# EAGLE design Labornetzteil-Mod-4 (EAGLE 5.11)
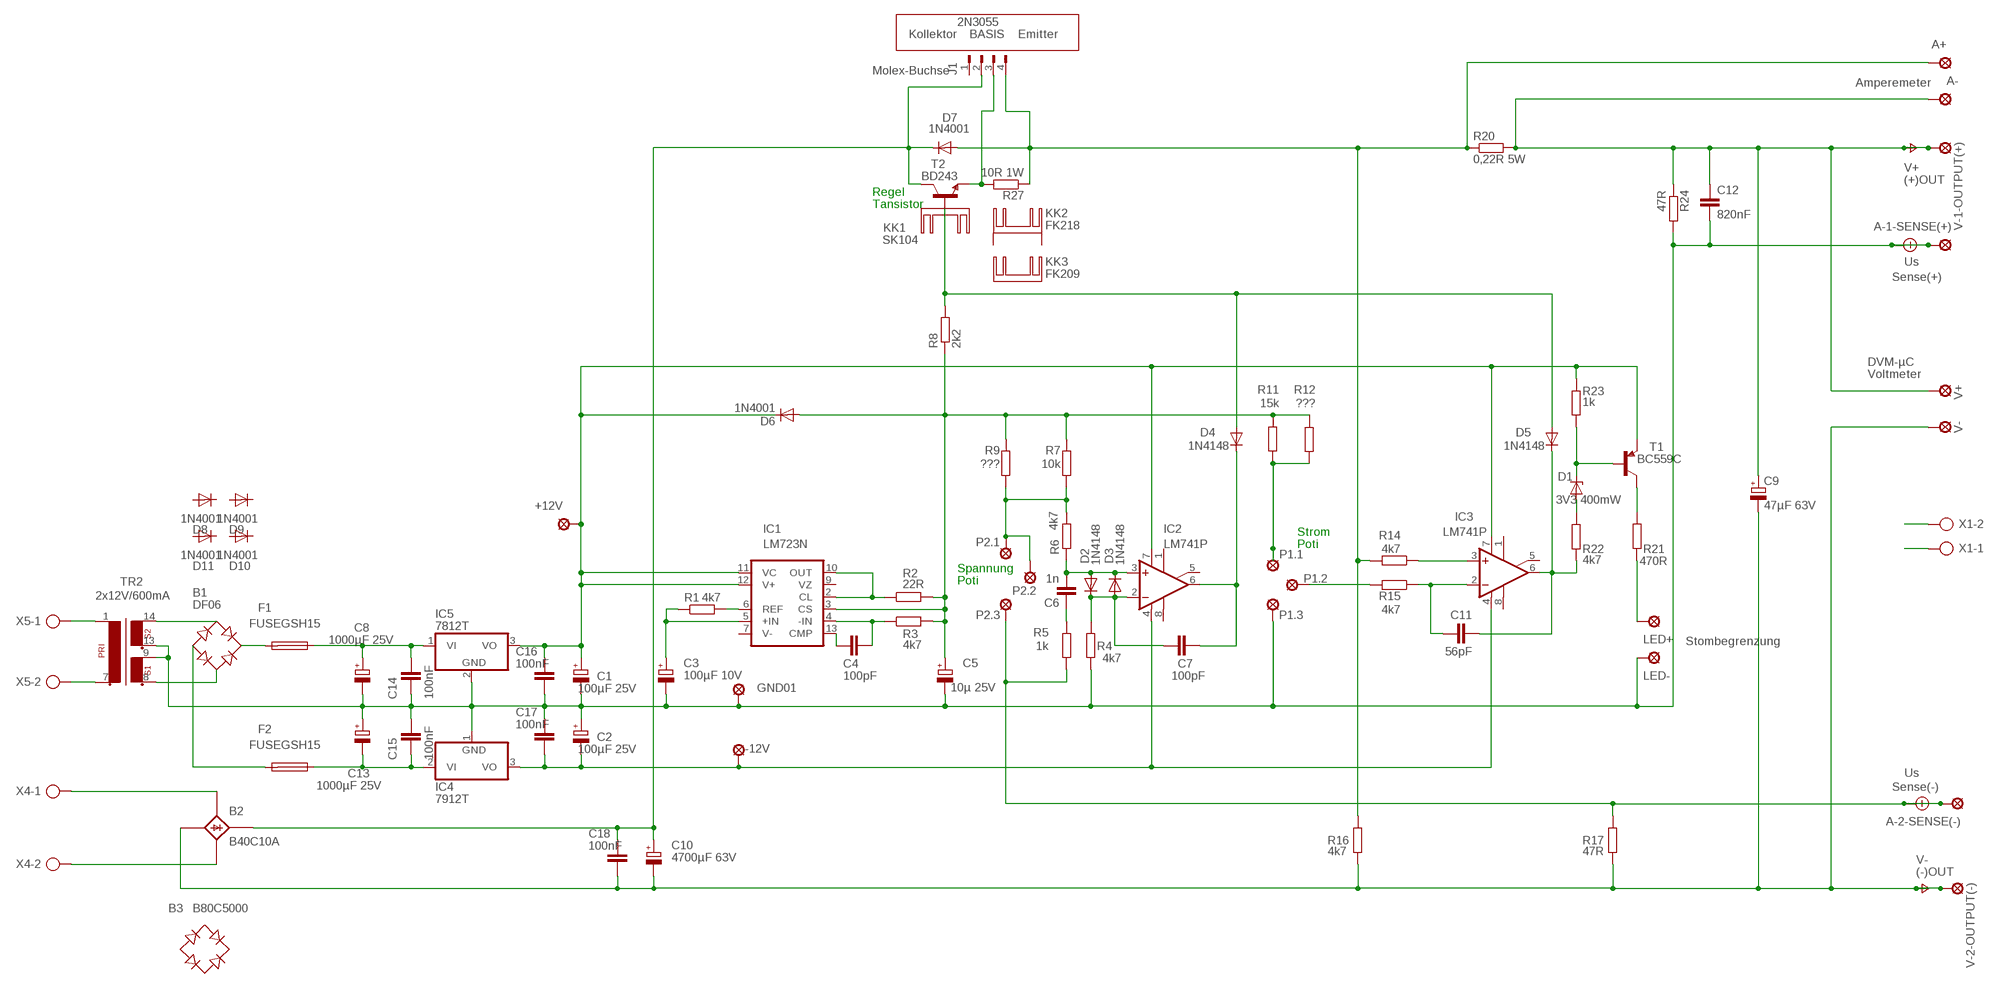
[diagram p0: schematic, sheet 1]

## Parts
+12V  SE14  [SE14]
-12V  SE14  [SE14]
A+  SE14  [SE14]
A-  SE14  [SE14]
A-1-SENSE(+)  SE14  [SE14]
A-2-SENSE(-)  SE14  [SE14]
B1  DF06  B-DIL  [B-DIL]
B2  B40C10A  B25A-  [B25A-]
B3  B80C5000  RECTIFIER-SKB32  [SKB32]
C1  100µF 25V  CPOL-EUE5-8.5  [E5-8,5]
C2  100µF 25V  CPOL-EUE5-8.5  [E5-8,5]
C3  100µF 10V  CPOL-EUE5-8.5  [E5-8,5]
C4  100pF  C-EU025-024X044  [C025-024X044]
C5  10µ 25V  CPOL-EUE5-8.5  [E5-8,5]
C6  1n  C-EU025-024X044  [C025-024X044]
C7  100pF  C-EU025-024X044  [C025-024X044]
C8  1000µF 25V  CPOL-EUE5-8.5  [E5-8,5]
C9  47µF 63V  CPOL-EUE3.5-8  [E3,5-8]
C10  4700µF 63V  CPOL-EUE10-35  [EB35D]
C11  56pF  C-EU025-024X044  [C025-024X044]
C12  820nF  C-EU025-024X044  [C025-024X044]
C13  1000µF 25V  CPOL-EUE5-8.5  [E5-8,5]
C14  100nF  C-EU025-030X050  [C025-030X050]
C15  100nF  C-EU025-030X050  [C025-030X050]
C16  100nF  C-EU025-030X050  [C025-030X050]
C17  100nF  C-EU025-030X050  [C025-030X050]
C18  100nF  C-EU025-030X050  [C025-030X050]
D1  3V3 400mW  ZENER-DIODEDO34-7  [DO34Z7]
D2  1N4148  1N4148DO35-10  [DO35-10]
D3  1N4148  1N4148DO35-10  [DO35-10]
D4  1N4148  1N4148DO35-10  [DO35-10]
D5  1N4148  1N4148DO35-10  [DO35-10]
D6  1N4001  1N4004  [DO41-10]
D7  1N4001  1N4004  [DO41-10]
D8  1N4001  1N4004  [DO41-10]
D9  1N4001  1N4004  [DO41-10]
D10  1N4001  1N4004  [DO41-10]
D11  1N4001  1N4004  [DO41-10]
F1  FUSEGSH15  [GSH15]
F2  FUSEGSH15  [GSH15]
GND01  SE14  [SE14]
IC1  LM723N  [DIL14]
IC2  LM741P  [DIL08]
IC3  LM741P  [DIL08]
IC4  7912T  7915T  [TO220H]
IC5  7812T  7815T  [TO220H]
J1  FLOPPY-4  [FLOPPY-4]
KK1  SK104  [SK104]
KK2  FK218  [FK218]
KK3  FK209  [FK209]
LED+  SE14  [SE14]
LED-  SE14  [SE14]
P1.1  SE14  [SE14]
P1.2  SE14  [SE14]
P1.3  SE14  [SE14]
P2.1  SE14  [SE14]
P2.2  SE14  [SE14]
P2.3  SE14  [SE14]
R1  4k7  R-EU_0204/2V  [0204V]
R2  22R  R-EU_0204/2V  [0204V]
R3  4k7  R-EU_0204/2V  [0204V]
R4  4k7  R-EU_0207/10  [0207/10]
R5  1k  R-EU_0207/10  [0207/10]
R6  4k7  R-EU_0207/10  [0207/10]
R7  10k  R-EU_0207/10  [0207/10]
R8  2k2  R-EU_0207/10  [0207/10]
R9  ???  R-EU_0207/10  [0207/10]
R11  15k  R-EU_0207/10  [0207/10]
R12  ???  R-EU_0207/10  [0207/10]
R14  4k7  R-EU_0207/10  [0207/10]
R15  4k7  R-EU_0207/10  [0207/10]
R16  4k7  R-EU_0207/10  [0207/10]
R17  47R  R-EU_0207/10  [0207/10]
R20  0,22R 5W  R-EU_0617/22  [0617/22]
R21  470R  R-EU_0207/10  [0207/10]
R22  4k7  R-EU_0207/10  [0207/10]
R23  1k  R-EU_0207/10  [0207/10]
R24  47R  R-EU_0207/10  [0207/10]
R27  10R 1W  R-EU_0309/12  [0309/12]
T1  BC559C  -PNP-TO92  [TO92]
T2  BD243  [TO220]
TR2  2x12V/600mA  EI54-2  [EI54-2]
V+  SE14  [SE14]
V-  SE14  [SE14]
V-1-OUTPUT(+)  V(+) Output  SE14  [SE14]
V-2-OUTPUT(-)  V(-) Output  SE14  [SE14]
X1  AK300/2  [AK300/2]
X4  AK300/2  [AK300/2]
X5  AK300/2  [AK300/2]

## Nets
+US: A-1-SENSE(+).MP C1.- C2.+ C3.- C5.- C8.- C12.2 C13.+ C14.1 C15.2 C16.1 C17.2 GND01.MP IC4.1(GND) IC5.2(GND) LED-.MP P1.3.MP R4.1 R24.2 TR2.9 TR2.13 ; supply symbol labelled Us
-US: A-2-SENSE(-).MP P2.3.MP R5.1 R17.1 ; supply symbol labelled Us
GND: B2.-1(-) C9.- C10.- C18.1 R16.2 R17.2 V-2-OUTPUT(-).MP V-.MP X1.1 ; supply symbol labelled V-
N$1: C3.+ IC1.5(+IN) R1.1
N$2: B1.AC1 TR2.14
N$3: B1.AC2 TR2.8
N$4: TR2.1 X5.1
N$5: IC1.6(REF) R1.2
N$6: -12V.MP C2.- C17.1 IC2.4(V-) IC3.4(V-) IC4.3(VO)
N$7: C6.1 R5.2
N$8: P2.1.MP P2.2.MP R6.2 R7.1 R9.1
N$9: IC1.2(CL) IC1.10(OUT) R2.1
N$10: C4.2 IC1.4(-IN) R3.1
N$11: TR2.7 X5.2
N$12: C4.1 IC1.13(CMP)
N$13: LED+.MP R21.1
N$14: C5.+ D6.A IC1.3(CS) R2.2 R3.2 R7.2 R8.1 R9.2 R11.2 R12.1
N$15: C6.2 D2.A D3.C IC2.3(+IN) R6.1
N$16: C7.1 D2.C D3.A IC2.2(-IN) R4.2
N$17: D4.A D5.A R8.2 T2.1(B)
N$18: C7.2 D4.C IC2.6(OUT)
N$19: P1.1.MP R11.1 R12.2
N$21: R21.2 T1.3(C)
N$22: IC3.3(+IN) R14.1
N$23: D1.C R23.2 T1.2(B)
N$24: P1.2.MP R15.2
N$25: D1.A R22.1
N$27: A+.MP D7.A J1.4 R14.2 R16.1 R20.1 R27.1
N$31: B2.AC1-(AC1) X4.1
N$32: B2.AC2-(AC2) X4.2
N$33: C11.1 IC3.2(-IN) R15.1
N$34: C11.2 D5.C IC3.6(OUT) R22.2
N$35: +12V.MP C1.+ C16.2 D6.C IC1.11(VC) IC1.12(V+) IC2.7(V+) IC3.7(V+) IC5.3(VO) R23.1 T1.1(E)
N$37: B2.+1(+) C10.+ C18.2 D7.C J1.2 T2.2(C)
N$38: C8.+ C14.2 F1.1 IC5.1(VI)
N$39: B1.- F2.2
N$40: C13.- C15.1 F2.1 IC4.2(VI)
N$41: B1.+ F1.2
N$42: J1.3 R27.2 T2.3(E)
V+: A-.MP C9.+ C12.1 R20.2 R24.1 V+.MP V-1-OUTPUT(+).MP X1.2
Unconnected: B2.+ B2.- B2.AC1 B2.AC2 B3.+ B3.- B3.AC1 B3.AC2 D8.A D8.C D9.A D9.C D10.A D10.C D11.A D11.C IC1.7(V-) IC1.9(VZ) IC2.1(ON1) IC2.5(ON2) IC2.8(OPT) IC3.1(ON1) IC3.5(ON2) IC3.8(OPT) J1.1 KK2.A2,2(K) KK2.B2,2(K)

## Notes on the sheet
- 2N3055
- Kollektor | BASIS | Emitter
- Molex-Buchse
- Amperemeter
- (+)OUT
- Regel
- Tansistor
- Sense(+)
- DVM-µC
- Voltmeter
- Strom
- Poti
- Spannung
- Poti
- Stombegrenzung
- Sense(-)
- (-)OUT

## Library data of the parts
+12V -12V A+ A- A-1-SENSE(+) A-2-SENSE(-) GND01 LED+ LED- P1.1-P1.3 P2.1-P2.3 V+ V- V-1-OUTPUT(+) V-2-OUTPUT(-) = solpad:SE14: SOLDER PAD
B1 = rectifier:B-DIL: RECTIFIER
B2 = rectifier:B25A-: RECTIFIER 25-A bridge
B3 = rectifier:RECTIFIER-: Rectifier
C1-C3 C5 C8-C10 C13 = rcl:CPOL-EU: POLARIZED CAPACITOR, European symbol
C4 C6 C7 C11 C12 C14-C18 = rcl:C-EU: CAPACITOR, European symbol
D1 = diode:ZENER-DIODE: Z-Diode
D2-D5 = diode:1N4148: DIODE
D6-D11 = diode:1N4004: DIODE
F1 F2 = fuse:FUSE: Fuse; OC_FARNELL: unknown; OC_NEWARK: unknown
IC1 = linear:*723: Positive VOLTAGE REGULATOR
IC2 IC3 = linear:*741: OP AMP
IC4 = linear:79*: Negative VOLTAGE REGULATOR
IC5 = linear:78*: Positive VOLTAGE REGULATOR Source: http://cache.national.com/ds/LM/LM78L05.pdf http://www.fairchildsemi.com/ds/LM/LM7805.pdf
J1 = con-amp:FLOPPY-4: MATE N-LOCK Floppy / HDD conector Distributor: Bürklin 71F970; OC_FARNELL: unknown; OC_NEWARK: unknown
KK1 = heatsink:SK104: HEATSINK
KK2 = heatsink:FK218: HEATSINK
KK3 = heatsink:FK209: HEATSINK
R1-R9 R11 R12 R14-R17 R20-R24 R27 = rcl:R-EU_: RESISTOR, European symbol
T1 = transistor:*-PNP-: PNP Transistror
T2 = transistor:BD243: NPN TRANSISTOR Source: Motorola Semiconductor, Master Selection Guide Q3/95 SG73 REV 8 page 5.5-4
TR2 = trafo:EI54-2: TRANSFORMER 1 primary winding, 2 secondary windings ERA
X1 X4 X5 = con-ptr500:AK300/2: CONNECTOR; OC_FARNELL: unknown; OC_NEWARK: unknown

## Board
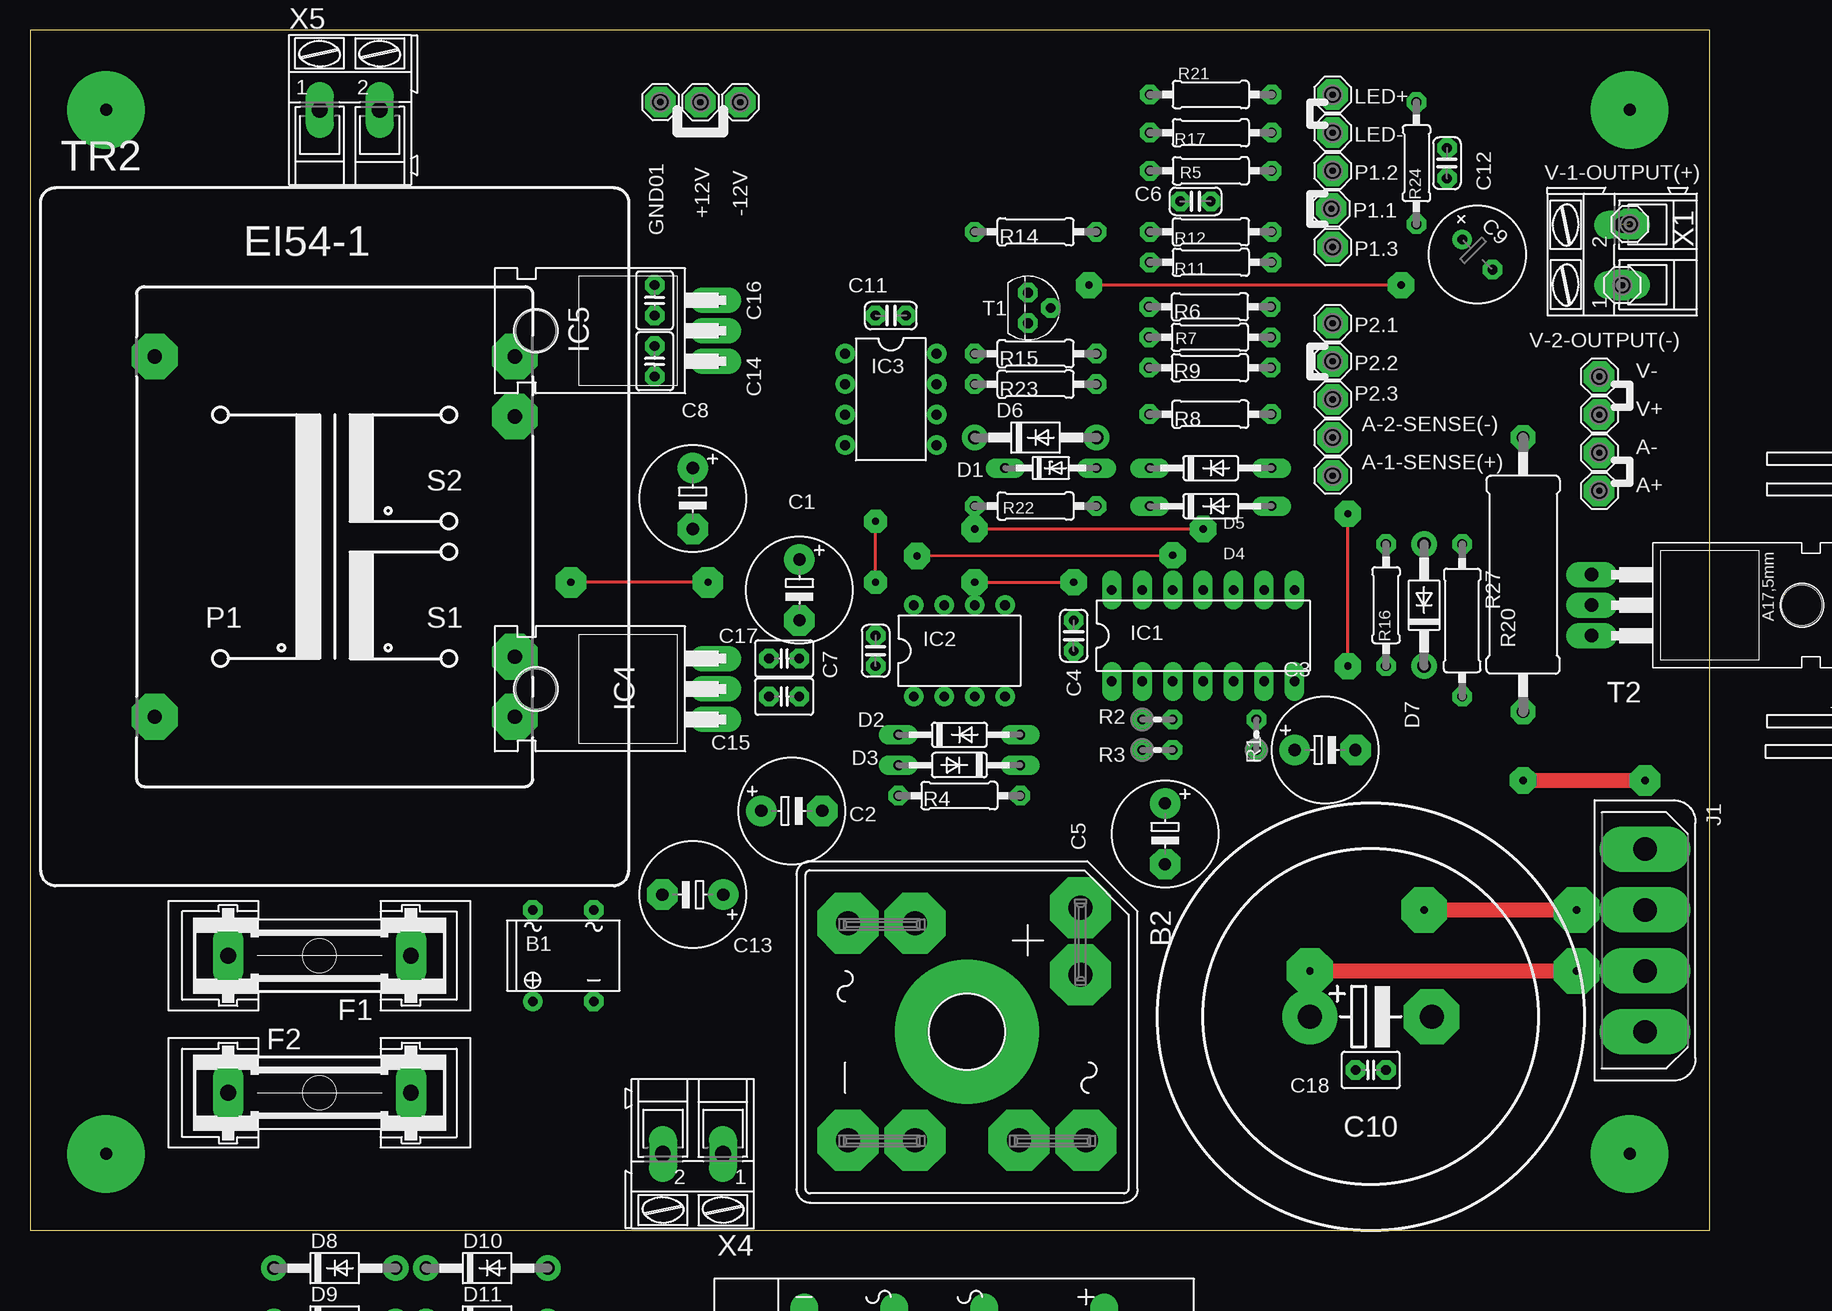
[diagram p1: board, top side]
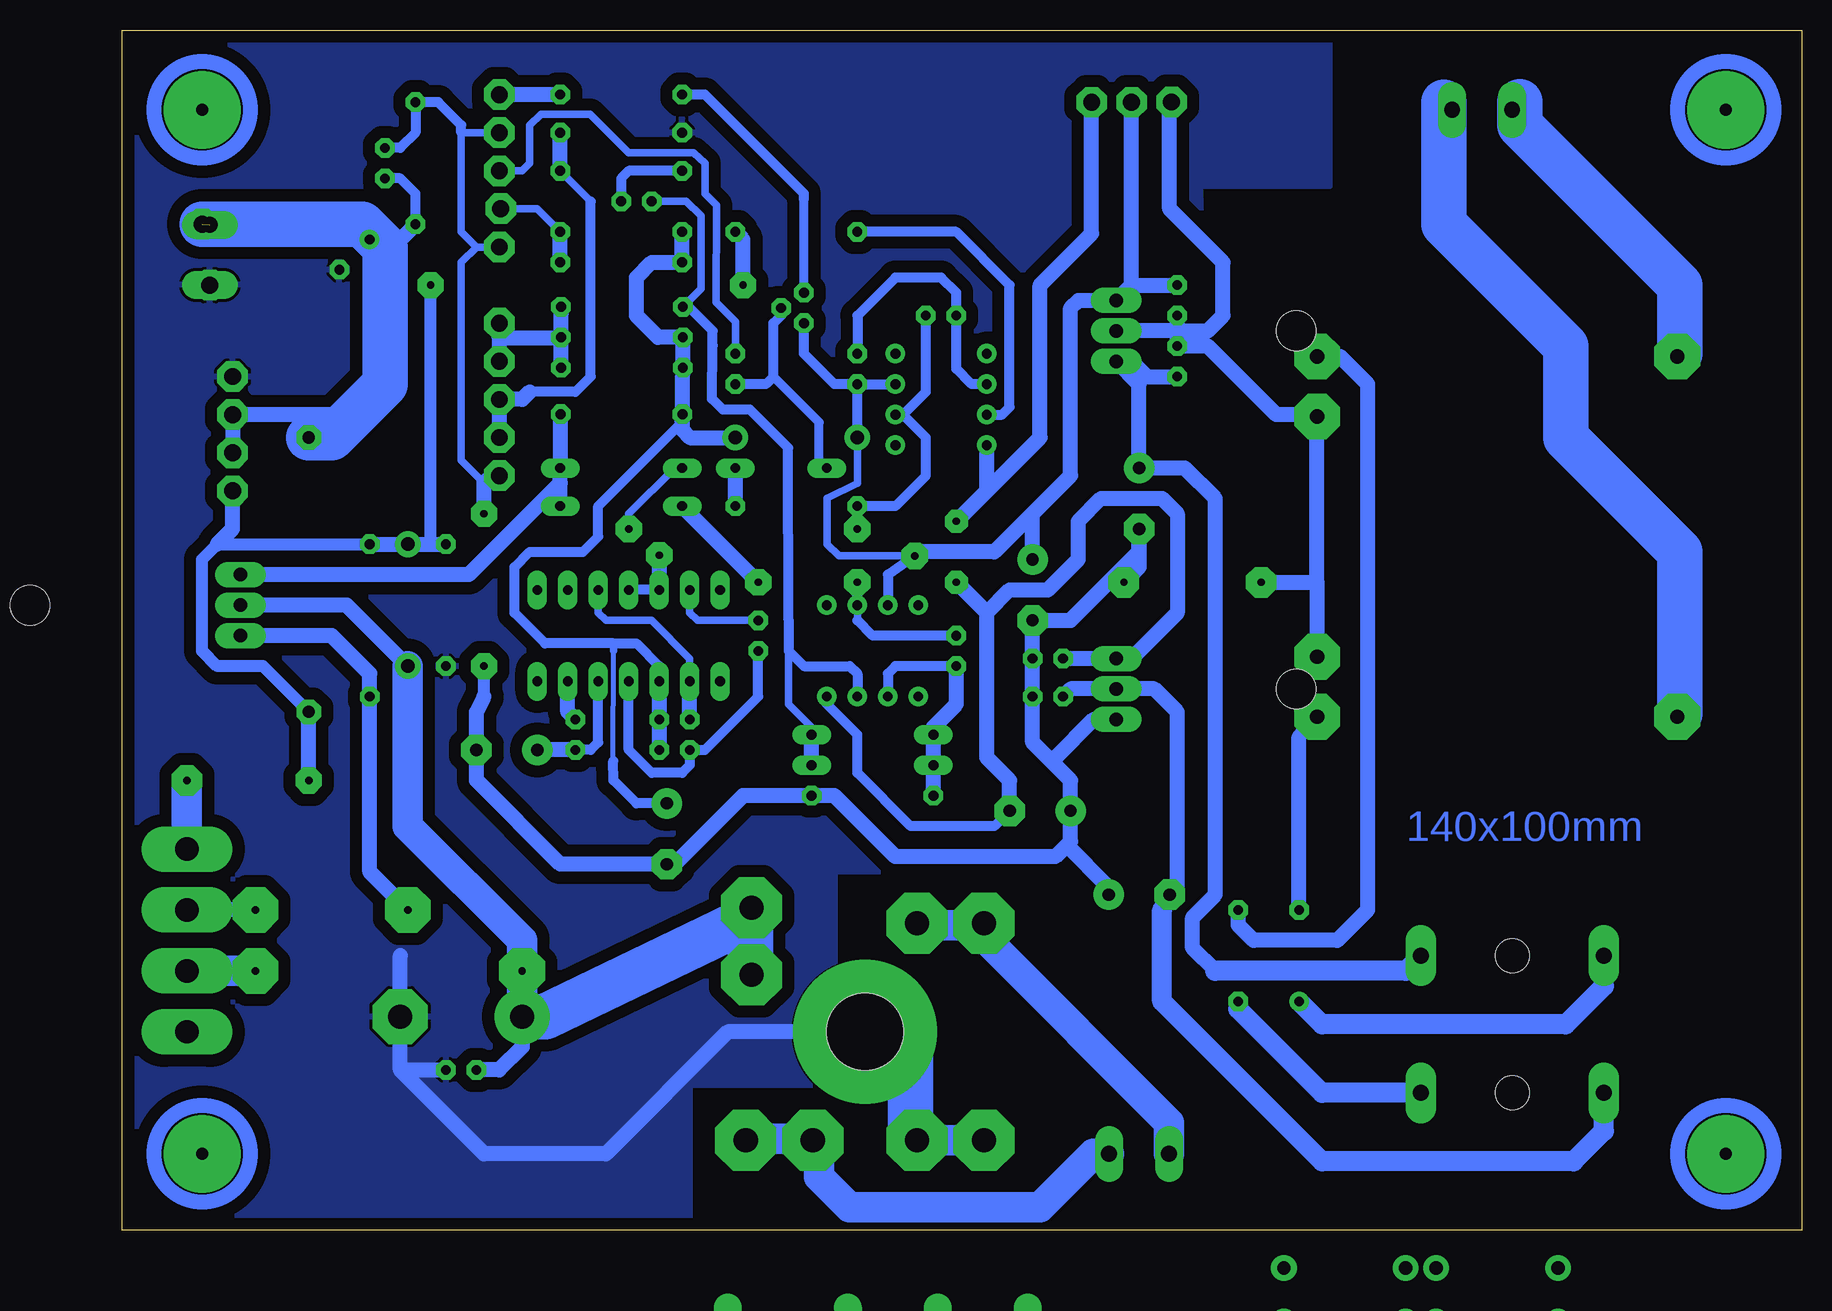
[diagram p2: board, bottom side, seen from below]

Size 140 x 100 mm. Coordinates in mm from the lower left corner, seen from the top.
Outline: 0,0 140,0 140,100 0,100 0,0
Copper layers (1*16): Top 0.035mm / dielectric 1.5mm / Bottom 0.035mm
Design rules "default *": minimum track width 30mil, minimum drill 24mil, track to track 8mil, track to pad 8mil, pad to pad 8mil, via to via 8mil, smd to smd 8mil, copper to edge 0.5mm, drill to drill 8mil, minimum pad ring 10mil, minimum via ring 8mil, stop-mask expansion 4mil, vias tented up to drill 0mil, thermal gap 10mil

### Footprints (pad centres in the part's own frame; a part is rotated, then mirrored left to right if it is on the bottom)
SE14 = drill 1.397 pad 2.54 octagon: MP 0,0
B-DIL = drill 0.813 round: + -2.54,-3.81 | drill 0.813 octagon: - 2.54,-3.81; AC1 2.54,3.81; AC2 -2.54,3.81
B25A- = drill 2.007 pad 5.08 octagon: + -10.338,9.449; +1 -4.75,9.449; - 9.042,-4.343; -1 9.042,-9.931; AC1 9.042,4.343; AC1- 9.042,9.931; AC2 -9.042,-4.343; AC2- -9.042,-9.931 | hole 6.401: 0,0
SKB32 = drill 1.321 long: + -13.97,0; - 11.024,0; AC1 -3.962,0; AC2 3.531,0
E5-8,5 = drill 1.016 pad 2.54 round: + -2.54,0 | drill 1.016 pad 2.54 octagon: - 2.54,0
C025-024X044 = drill 0.813 octagon: 1 -1.27,0; 2 1.27,0
E3,5-8 = drill 0.813 pad 1.6 round: + -1.778,0 | drill 0.813 pad 1.6 octagon: - 1.778,0
EB35D = drill 2.007 pad 4.597 round: + -5.08,0 | drill 2.007 pad 4.597 octagon: - 5.08,0
C025-030X050 = drill 0.813 octagon: 1 -1.27,0; 2 1.27,0
DO34Z7 = drill 0.813 long: A 3.81,0; C -3.81,0
DO35-10 = drill 0.813 long: A 5.08,0; C -5.08,0
DO41-10 = drill 1.118 round: A 5.08,0; C -5.08,0
GSH15 = drill 1.321 pad 2.54 long: 1 -7.62,0; 2 7.62,0 | hole 2.794: 0,0
DIL14 = drill 0.813 long: 1 -7.62,-3.81; 2 -5.08,-3.81; 3 -2.54,-3.81; 4 0,-3.81; 5 2.54,-3.81; 6 5.08,-3.81; 7 7.62,-3.81; 8 7.62,3.81; 9 5.08,3.81; 10 2.54,3.81; 11 0,3.81; 12 -2.54,3.81; 13 -5.08,3.81; 14 -7.62,3.81
DIL08 = drill 0.813 pad 1.27 round: 1 -3.81,-3.81; 2 -1.27,-3.81; 3 1.27,-3.81; 4 3.81,-3.81; 5 3.81,3.81; 6 1.27,3.81; 7 -1.27,3.81; 8 -3.81,3.81
TO220H = drill 1.118 long: 1 -2.54,-10.16; 2 0,-10.16; 3 2.54,-10.16 | hole 3.302: 0,4.826
FLOPPY-4 = drill 1.93 pad 3.81 long: 1 7.62,0; 2 2.54,0; 3 -2.54,0; 4 -7.62,0
SK104 = hole 2.54: -12.7,-0.762; 12.7,-0.762
FK218 = drill 2.21 pad 3.81 round: A2,2 -8.89,-0.508; B2,2 8.89,-0.508
0204V = drill 0.813 octagon: 1 -1.27,0; 2 1.27,0
0207/10 = drill 0.813 octagon: 1 -5.08,0; 2 5.08,0
0617/22 = drill 1.016 octagon: 1 -11.43,0; 2 11.43,0
0309/12 = drill 0.813 octagon: 1 -6.35,0; 2 6.35,0
TO92 = drill 0.813 octagon: 1 1.27,0; 2 0,1.905; 3 -1.27,0
TO220 = drill 1.118 long: 1 -2.54,-6.35; 2 0,-6.35; 3 2.54,-6.35 | hole 3.302: 0,11.176
EI54-2 = drill 1.194 pad 3.81 octagon: 1 -15.011,15.011; 7 -15.011,-15.011; 8 15.011,-15.011; 9 15.011,-10.008; 13 15.011,10.008; 14 15.011,15.011
AK300/2 = drill 1.321 long: 1 -2.515,0; 2 2.489,0

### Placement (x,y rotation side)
+12V  55.88,93.98 0 top
-12V  59.2,93.98 0 top
A+  130.81,61.59 0 top
A-  130.81,64.77 0 top
A-1-SENSE(+)  108.58,62.87 0 top
A-2-SENSE(-)  108.58,66.04 0 top
B1  44.45,22.86 0 top
B2  78.11,16.51 270 top
B3  not placed on the board
C1  64.14,53.34 270 top
C2  63.5,34.92 0 top
C3  107.95,40.01 0 top
C4  87,49.53 270 top
C5  94.61,33.02 270 top
C6  97.16,85.72 180 top
C7  70.48,48.26 90 top
C8  55.24,60.96 270 top
C9  120.65,81.28 315.1 top
C10  111.76,17.78 0 top
C11  71.75,76.2 0 top
C12  118.11,88.9 90 top
C13  55.24,27.94 180 top
C14  52.07,72.39 270 top
C15  62.87,44.45 0 top
C16  52.07,77.47 90 top
C17  62.87,47.62 0 top
C18  111.76,13.34 180 top
D1  85.09,63.5 0 top
D2  77.47,41.27 0 top
D3  77.47,38.73 180 top
D4  98.42,60.33 0 top
D5  98.42,63.5 0 top
D6  83.82,66.04 0 top
D7  116.2,52.07 90 top
D8  not placed on the board
D9  not placed on the board
D10  not placed on the board
D11  not placed on the board
F1  24.13,22.86 180 top
F2  24.13,11.43 0 top
GND01  52.55,93.99 0 top
IC1  97.79,49.53 0 top
IC2  77.47,48.26 0 top
IC3  71.75,69.22 270 top
IC4  46.99,45.09 90 top
IC5  46.99,74.93 90 top
J1  134.62,24.13 270 top
KK1  not placed on the board
KK2  not placed on the board
KK3  not placed on the board
LED+  108.58,94.61 0 top
LED-  108.58,91.44 0 top
P1.1  108.47,85.11 0 top
P1.2  108.58,88.27 0 top
P1.3  108.58,81.92 0 top
P2.1  108.58,75.56 0 top
P2.2  108.58,72.39 0 top
P2.3  108.58,69.22 0 top
R1  102.23,41.27 90 top
R2  93.98,42.55 0 top
R3  93.98,40.01 0 top
R4  77.47,36.2 180 top
R5  98.42,88.27 180 top
R6  98.36,76.94 0 top
R7  98.36,74.39 180 top
R8  98.39,67.99 0 top
R9  98.36,71.86 180 top
R11  98.42,80.64 180 top
R12  98.42,83.19 0 top
R14  83.82,83.19 0 top
R15  83.82,73.03 0 top
R16  113.03,52.07 270 top
R17  98.42,91.44 180 top
R20  124.46,54.61 90 top
R21  98.42,94.61 180 top
R22  83.82,60.33 180 top
R23  83.82,70.48 0 top
R24  115.57,88.9 90 top
R27  119.38,50.8 270 top
T1  83.19,76.83 270 top
T2  136.53,52.07 270 top
TR2  25.4,57.78 0 top
V+  130.81,67.94 0 top
V-  130.81,71.12 0 top
V-1-OUTPUT(+)  133.35,83.82 0 top
V-2-OUTPUT(-)  132.72,78.74 0 top
X1  132.72,81.28 90 top
X4  55.24,6.35 180 top
X5  26.67,93.34 0 top

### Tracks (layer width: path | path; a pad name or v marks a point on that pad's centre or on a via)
+US  (via drill 0.61 pad 2.18, 0.61 pad 2.54)
  Top 0.254: v109.86,46.99 v109.86,59.69 | v56.52,53.98 v45.09,53.98
  Bottom 0.61: LED-.MP 111.76,91.44 111.76,83.19 110.49,81.92 | 110.49,81.92 P1.3.MP | 110.49,81.92 111.76,80.64 111.76,64.14 109.86,62.23
  Bottom 0.813: 111.76,91.44 111.76,92.08 113.67,93.98 R24.2 115.57,91.44 116.84,90.17 C12.2
  Bottom 1.016: 109.86,44.45 v109.86,46.99
  Bottom 1.27: 40.41,53.98 TR2.9 | 40.41,53.98 TR2.13 40.56,67.94 43.81,67.94 49.53,73.66 C14.1 52.07,74.93 | 61.28,32.07 60.96,32.38 C2.+ 60.96,37.47 62.23,38.73 | 61.28,32.07 62.23,31.11 75.56,31.11 80.64,36.2 R4.1 88.27,36.2 93.98,30.48 C5.- 103.5,30.48 110.49,37.47 C3.- 110.49,43.18 109.86,44.45 | 62.23,38.73 64.14,40.64 C15.2 C17.2 C1.- 60.96,50.8 55.24,56.52 C8.- 55.24,55.24 v56.52,53.98 | 52.07,74.93 C16.1 | 52.07,74.93 IC5.2 | C13.+ 57.78,28.57 61.28,32.07 | 52.55,93.82 GND01.MP 52.7,93.83 52.7,85.09 48.26,80.64 48.26,76.2 49.53,74.93 52.07,74.93 | v45.09,53.98 40.41,53.98 | v109.86,59.69 109.86,62.23 109.22,62.87 A-1-SENSE(+).MP | IC4.1 59.05,42.55 62.23,39.37 62.23,38.73
-US
  Bottom 0.61: 100.97,85.72 R5.1
  Bottom 0.813: 106.05,69.85 102.23,69.85 100.97,71.12 100.97,85.72
  Bottom 1.27: R5.1 R17.1 | 106.05,69.85 106.68,69.22 P2.3.MP A-2-SENSE(-).MP
GND  (via drill 0.1 pad 12)
  Bottom 1.27: 116.84,22.86 C10.- 116.84,13.34 | 116.84,13.34 C18.1 | v78.11,16.51 89.53,16.51 99.69,6.35 109.86,6.35 116.84,13.34
  Bottom 2.54: B2.-1 73.66,7.47 73.66,7.62
  Bottom 3.81: 73.66,7.62 74.3,7.62 74.3,15.24 v78.11,16.51
  pour Bottom (isolate 1.016): 39.37,100.97 39.37,87 50.16,87 48.9,29.84 80.64,29.84 80.64,12.06 92.71,12.06 92.71,-1.27 140.97,-1.27 141.6,101.6
N$1
  Bottom 0.813: IC1.5 100.33,40.64 100.97,40.01 R1.1
  Bottom 1.27: R1.1 C3.+
N$2
  Bottom 1.27: TR2.14 38.51,72.8 36.2,70.48 36.2,26.67 38.73,24.13 45.72,24.13 46.99,25.4 B1.AC1
N$3
  Bottom 1.27: B1.AC2 41.91,41.1 TR2.8
N$4
  Bottom 1.27: X5.1 22.86,92.08 21.59,90.81 23.5,92.08
  Bottom 3.81: 23.52,94 23.5,92.08 10.16,78.74 10.16,73.03 TR2.1
N$5
  Bottom 1.27: R1.2 102.87,43.18 IC1.6
N$6  (via drill 0.61 pad 1.93)
  Top 0.254: v70.48,59.05 v70.48,53.98 70.48,53.34
  Bottom 0.813: C2.- 67.31,33.66 74.3,33.66 78.74,38.1 78.74,41.27 81.28,43.81 IC2.4
  Bottom 1.27: C2.- 66.04,37.47 67.94,39.37 67.94,51.44 | 67.94,51.44 66.04,53.34 62.87,53.34 60.33,55.88 60.33,59.05 58.42,60.96 53.34,60.96 52.07,59.69 52.07,51.44 55.88,47.62 IC4.3 C17.1 | 67.94,61.59 IC3.4 | v70.48,59.05 67.94,61.59 | 67.94,51.44 v70.48,53.98 | -12V.MP 59.2,83.04 63.5,78.74 63.5,66.04 67.94,61.59
N$7
  Bottom 0.813: C6.1 98.42,87.63 97.79,88.27 R5.2
N$8
  Bottom 1.27: 103.44,76.91 R7.1 R9.1 | 108.58,74.3 P2.2.MP | 108.58,74.3 P2.1.MP | 103.44,76.91 R6.2 | 103.44,76.91 103.5,74.3 108.58,74.3
N$9
  Bottom 0.61: IC1.10 100.33,51.44 99.69,50.8 95.89,50.8 92.71,47.62 IC1.2
  Bottom 1.27: R2.1 IC1.2
N$10
  Bottom 0.813: C4.2 87,44.45 91.44,40.01 R3.1 92.71,38.73 93.34,38.1 95.89,38.1 97.79,40.01 IC1.4
N$11
  Bottom 0.813: 29.84,93.98 29.21,93.34 X5.2
  Bottom 3.81: TR2.7 10.16,43 10.16,56.52 19.68,66.04 19.68,73.66 29.84,83.82 29.84,93.98
N$12
  Bottom 0.61: C4.1 92.08,50.8 92.71,51.44 IC1.13
N$13
  Bottom 1.27: R21.1 LED+.MP
N$14
  Bottom 0.406: 99.09,39.08 99.06,48.26
  Bottom 0.61: 99.06,48.26 99.06,48.9
  Bottom 0.813: IC1.3 95.25,46.99 97.16,48.9 99.06,48.9 104.78,48.9 107.31,51.44 107.31,55.24 106.05,56.52 101.6,56.52 100.33,57.78 100.33,60.33 93.34,67.31 | C5.+ 97.16,35.56 99.06,37.47 99.09,39.08
  Bottom 1.27: R3.2 R2.2 IC1.3 | D6.A 92.71,66.04 93.34,66.67 93.34,67.31 93.34,67.95 R8.1 93.31,70.55 R9.2 R7.2 95.35,74.39 97.16,76.2 97.16,79.38 95.89,80.64 R11.2 R12.1
N$15
  Bottom 0.61: C6.2 93.02,85.72 91.75,84.51 91.75,78.43 93.25,76.94 R6.1 | D2.A 82.55,41.91 84.45,43.81 84.45,50.8
  Bottom 0.813: 93.44,76.94 R6.1 93.17,76.83 92.71,76.83 90.81,74.93 90.81,73.71 90.86,69.27 89.95,68.36 87.68,68.36 84.51,65.18 84.45,50.8 84.45,48.26 83.19,46.99 79.38,46.99 78.74,46.35 IC2.3
  Bottom 1.27: D3.C D2.A
N$16
  Bottom 0.813: IC2.2 76.2,46.35 75.56,46.99 C7.1
  Bottom 1.27: R4.2 D3.A D2.C 72.39,41.91 70.48,43.81 C7.1
N$17
  Bottom 0.762: R8.2
  Bottom 1.27: D4.A 103.5,62.23 | 103.5,62.23 D5.A 103.47,62.91 R8.2 | T2.1 111.12,54.61 103.5,62.23
N$18  (via drill 0.61 pad 2.18)
  Top 0.254: v78.74,53.98 v87,53.98
  Bottom 0.61: 78.74,50.8 IC2.6
  Bottom 0.813: IC2.6 v78.74,53.98 | 78.74,50.8 77.47,49.53 C7.2
  Bottom 1.27: v87,53.98 D4.C
N$19
  Bottom 0.61: R12.2 105.41,85.09 108.44,85.09
  Bottom 1.27: R11.1 R12.2 | 108.44,85.09 P1.1.MP
N$20  (via drill 1 pad 6.45)
  other vias: 6.35,93.34
N$21
  Bottom 0.762: T1.3 83.19,85.91 | R21.2 92.71,94.61
  Bottom 0.813: 83.19,85.91 83.19,86.36 91.44,94.61 R21.2
N$22
  Bottom 0.813: R14.1 70.48,83.19 66.04,78.74 66.04,68.58 66.67,67.94 IC3.3
N$23
  Bottom 0.762: D1.C 81.92,64.14 81.92,67.31 85.72,71.12
  Bottom 0.813: T1.2 85.09,76.2 85.72,75.56 85.72,71.12 86.36,70.48 R23.2
N$24
  Bottom 0.61: P1.2.MP 106.68,88.27 106.05,88.9 106.05,92.08 105.1,92.97 101.03,92.97 97.81,89.76 92.4,89.76 91.44,88.9 91.44,86.36 90.48,85.4 90.53,77.31 88.9,75.68 R15.2
N$25
  Bottom 1.27: R22.1 D1.A
N$26  (via drill 1 pad 6.45)
  other vias: 133.35,93.34
N$27  (via drill 0.61 pad 2.18, 0.61 pad 2.54)
  Top 0.254: v114.3,78.74 v88.27,78.74
  Top 1.27: v124.46,37.47 v134.62,37.47
  Bottom 1.016: R20.1 128.27,46.99 132.08,46.99 133.35,48.26 133.35,55.88 132.08,57.15 R27.1 | 114.3,57.15 v114.3,78.74
  Bottom 1.27: R27.1 D7.A 114.3,57.15 R16.1 | R14.2 88.27,82.55 v88.27,78.74 | v124.46,37.47 R20.1 | A+.MP 130.81,58.42 132.08,57.15
  Bottom 2.54: v134.62,37.47 J1.4
N$28  (via drill 1 pad 6.45)
  other vias: 133.35,6.35
N$29  (via drill 1 pad 6.45)
  other vias: 6.35,6.35
N$31
  Bottom 2.54: X4.1 59.05,6.35 63.5,1.91 79.38,1.91 81.92,4.45 81.92,7.62 86.61,7.62 B2.AC1-
N$32
  Bottom 2.54: X4.2 52.76,8.94 67.94,24.13 69.6,25.4 | 69.6,25.4 72.39,25.4 | 69.6,25.4 B2.AC2-
N$33
  Bottom 0.813: IC3.2 69.22,70.48 70.48,71.75 C11.1 70.48,78.11 71.75,79.38 75.56,79.38 78.74,76.2 R15.1
N$34  (via drill 0.61 pad 2.18)
  Top 0.254: v78.74,58.42 v97.79,58.42
  Bottom 0.61: D5.C 93.98,63.5 97.79,59.69 v97.79,58.42
  Bottom 0.762: R22.2 v78.74,58.42
  Bottom 0.813: R22.2 75.56,60.33 73.03,62.87 73.03,66.04 74.93,67.94 | 74.93,67.94 IC3.6 | 74.93,67.94 73.03,69.85 C11.2
N$35  (via drill 0.61 pad 2.18)
  Top 0.254: v73.94,56.17 v95.25,56.23
  Bottom 0.61: v73.94,56.17 80.25,56.17 81.28,57.15 81.28,60.96 78.74,62.23 D6.C
  Bottom 0.813: IC1.12 IC1.11 | D6.C R23.1 | R23.1 80.64,70.48 83.19,73.03 T1.1 | R23.1 IC3.7 | IC2.7 76.2,54.61 v73.94,56.17
  Bottom 1.27: v95.25,56.23 IC1.12 | C1.+ 64.14,59.69 | v73.94,56.17 74.3,56.52 67.31,56.52 64.14,59.69 | C16.2 55.88,78.74 IC5.3 | IC5.3 60.33,77.47 60.96,76.83 60.96,62.87 64.14,59.69 | +12V.MP 55.88,78.11 IC5.3
N$37  (via drill 0.61 pad 3.81)
  Top 1.27: v106.68,21.59 v128.91,21.59
  Bottom 1.27: T2.2 121.28,52.07 D7.C | C18.2 108.58,13.34 106.68,15.24 C10.+
  Bottom 2.54: D7.C 116.2,33.66 106.68,24.13 v106.68,21.59 C10.+ | v128.91,21.59 J1.2
  Bottom 3.81: C10.+ 104.78,17.78 87.63,26.04 87.63,21.34 B2.+1
N$38
  Bottom 1.27: C14.2 54.61,71.12 55.88,72.39 IC5.1 55.24,70.48 C8.+ 51.44,63.5 48.9,60.96 48.9,27.94 50.8,26.04 50.8,23.5 48.9,21.59
  Bottom 1.676: 48.9,21.59 33.02,21.59 F1.1
N$39
  Bottom 1.27: 46.99,18.41 B1.-
  Bottom 1.676: 46.99,18.41 40.01,11.43 F2.2
N$40
  Bottom 1.27: C15.1 60.96,45.09 IC4.2 53.98,45.09 52.07,43.18 52.07,28.57 C13.- 53.34,26.67
  Bottom 1.676: 53.34,26.67 53.34,19.05 40.01,5.71 19.05,5.71 16.51,8.26 F2.1
N$41
  Bottom 1.676: B1.+ 40.01,17.14 19.68,17.14 16.51,20.32 F1.2
N$42  (via drill 0.61 pad 3.81)
  Top 1.27: v116.2,26.67 v128.91,26.67
  Bottom 1.27: v116.2,26.67 119.38,29.84 R27.2 119.38,46.35 122.56,49.53 T2.3 | v128.91,26.67 J1.3
V+  (1 unrouted)
  Bottom 0.813: C12.1 116.84,87.63 115.57,86.36 R24.1
  Bottom 1.27: R24.1 117.98,81.28 C9.+ 121.79,83.82 | R20.2 121.92,67.94 V+.MP A-.MP
  Bottom 3.81: R20.2 122.56,66.04 118.11,70.48 118.11,81.92 120.02,83.82 121.79,83.82 V-1-OUTPUT(+).MP
(copper drawn outside any net)
  shapes: Bottom circle x4

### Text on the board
Bottom: 140x100mm
bOrigins: 140x100mm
